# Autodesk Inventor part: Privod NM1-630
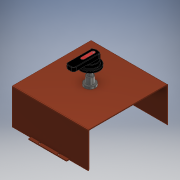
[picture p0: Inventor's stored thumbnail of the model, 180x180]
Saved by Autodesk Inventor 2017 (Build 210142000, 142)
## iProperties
Part Number: Privod NM1-630
Material: Типовые
Document SubType Name: Modeling
Designer: RSagdiev
Density: 1 g/cm^3
Appearance: По умолчанию
Author: RSagdiev
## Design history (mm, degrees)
sketch "Эскиз1"
  geometry: L1 (-45.5, 101.75)-(45.5, 101.75); L2 (45.5, 101.75)-(45.5, 93.25); L3 (45.5, 93.25)-(24.75, 93.25); L4 (-45.5, 93.25)-(-45.5, 101.75); L5 (0, 0)-(119.698, 0); L6 (0, 0)-(-104.809, 0); L7 (0, 94.88)-(0, -60.954); L8 (-24.75, 93.25)-(-20.75, 93.25); L9 (-20.75, 93.25)-(-20.75, 98.25); L10 (-22.75, 100.25)-(-22.75, 100.25); L11 (-24.75, 98.25)-(-24.75, 93.25); L12 (20.75, 93.25)-(20.75, 98.25); L13 (22.75, 100.25)-(22.75, 100.25); L14 (24.75, 93.25)-(20.75, 93.25); L15 (24.75, 98.25)-(24.75, 93.25); L16 (-24.75, 93.25)-(-45.5, 93.25); L17 (-20.75, 93.25)-(-24.75, 93.25); L18 (20.75, 93.25)-(-20.75, 93.25); L19 (24.75, 93.25)-(20.75, 93.25); A1 r 2 centre (-22.75, 98.25) between (-22.75, 100.25) and (-24.75, 98.25); A2 r 2 centre (-22.75, 98.25) between (-20.75, 98.25) and (-22.75, 100.25); A3 r 2 centre (22.75, 98.25) between (22.75, 100.25) and (20.75, 98.25); A4 r 2 centre (22.75, 98.25) between (24.75, 98.25) and (22.75, 100.25); 5 further points
  constraints: 38 end point, 10 point on line, 10 symmetric about line, 8 parallel, 8 point on circle, 4 centre point, 4 horizontal, 4 tangent, 2 perpendicular, 1 concentric, 1 midpoint, 1 vertical, 2 other
  dimensions: "d0" = 93.25 distance between parallel lines of L3 L6 (= 0.5 x Высота); "d1" = 8.5 distance of L1.end L2.end; "d2" = 91 distance between parallel lines of L2 L4 (= 0.5 x Ширина); "d3" = 4 distance of point (-24.75, 100.25) point (-20.75, 100.25); "d4" = 7 distance of point (-20.75, 100.25) L8.end; "d5" = 2 radius of A1 (derived); "d6" = 22.75 distance from line of L4 A1.centre (= 0.25 x d2)
extrude "Выдавливание1" new body sketch "Эскиз1" distance "d7" = 2; taper "d8" = 0 deg
mirror "Зеркальное отражение1"
sketch "Эскиз2"
  geometry: L1 (-45.5, 101.75)-(-45.5, 93.25) reference; L2 (45.5, 93.25)-(45.5, 101.75) reference; L3 (-45.5, -101.75)-(-45.5, -93.25) reference; L4 (45.5, -93.25)-(45.5, -101.75) reference; L5 (-91, 95.25)-(91, 95.25); L6 (91, 95.25)-(91, 93.25); L7 (91, 93.25)-(-91, 93.25); L8 (-91, 93.25)-(-91, 95.25); L9 (-45.5, 93.25)-(-24.75, 93.25) reference
  constraints: 8 end point, 2 parallel, 1 collinear, 1 horizontal, 1 perpendicular
  dimensions: "d13" = 182 distance of L5.start L5.end (= Ширина); "d14" = 2 distance of L5.end L6.end; "d15" = 45.5 distance between parallel lines of L1 L8 (= 0.25 x d13)
extrude "Выдавливание2" join sketch "Эскиз2" distance "d11" = 85 (computed from H1); taper "d12" = 0 deg
mirror "Зеркальное отражение2"
sketch "Эскиз3"
  geometry: L1 (-91, 95.25)-(-45.5, 95.25) reference; L2 (91, -95.25)-(-91, -95.25) reference; L3 (-91, 95.25)-(91, 95.25); L4 (91, 95.25)-(91, -95.25); L5 (91, -95.25)-(-91, -95.25); L6 (-91, -95.25)-(-91, 95.25); 1 further point
  constraints: 8 end point, 2 parallel, 1 horizontal, 1 perpendicular
extrude "Выдавливание3" join sketch "Эскиз3" distance "d16" = 2; taper "d17" = 0 deg
fillet "Сопряжение1" dims "d18" = 2
sketch "Эскиз4"
  geometry: L1 (91, -91.25)-(-91, -91.25) reference; L2 (91, -91.25)-(91, 91.25) reference; L3 (-91, 91.25)-(91, 91.25) reference; L4 (-91, 91.25)-(-91, -91.25) reference; L5 (-91, 91.25)-(-91, -91.25) reference; L6 (-91, -91.25)-(91, 91.25); L7 (91, -91.25)-(91, 91.25) reference; L8 (-91, 91.25)-(91, -91.25); C1 r 5 at (0, 0); 1 further point
  constraints: 4 end point, 1 centre point, 1 coincident
  dimensions: "d19" = 10 diameter of C1
extrude "Выдавливание4" cut sketch "Эскиз4" distance "d20" = 10; taper "d21" = 0 deg
sketch "Эскиз5"
  geometry: C1 r 5 at (0, 0) reference; C2 r 5 at (0, 0); C3 r 8 at (0, 0); 1 further point
  constraints: 2 centre point, 2 coincident
  dimensions: "d22" = 16 diameter of C3
extrude "Выдавливание5" new body sketch "Эскиз5" distance "d23" = 29.66667 (= 0.333333 x H1); taper "d24" = 0 deg
sketch "Эскиз6"
  geometry: C1 r 5 at (0, 0) reference; C2 r 5 at (0, 0); 1 further point
  constraints: 1 centre point, 1 coincident
extrude "Выдавливание6" new body sketch "Эскиз6" distance "d25" = 79.66667 (computed from H1); taper "d26" = 0 deg
sketch "Эскиз7"
  geometry: C1 r 5 at (0, 0) reference; C2 r 13 at (0, 0); C3 r 8 at (0, 0); C4 r 5 at (0, 0); 1 further point
  constraints: 3 centre point, 3 coincident
  dimensions: "d27" = 26 diameter of C2; "d28" = 16 diameter of C3; "d29" = 10 diameter of C4
extrude "Выдавливание7" new body sketch "Эскиз7" distance "d30" = 5; taper "d31" = 0 deg
extrude "Выдавливание8" join sketch "Эскиз7" distance "d32" = 20; taper "d33" = 0 deg
sketch "Эскиз8"
  geometry: C1 r 7 at (0, 0); 1 further point
  constraints: 1 centre point, 1 coincident
  dimensions: "d34" = 14 diameter of C1
extrude "Выдавливание9" new body sketch "Эскиз8" distance "d35" = 3; taper "d36" = 0 deg
fillet "Сопряжение2" dims "d37" = 3
sketch "Эскиз9"
  geometry: L1 (1, 13.17)-(-1, 13.17); L2 (-1, 13.17)-(-1, -13.17); L3 (-1, -13.17)-(1, -13.17); L4 (1, -13.17)-(1, 13.17); L5 (1, 13.17)-(-1, -13.17); L6 (-1, 13.17)-(1, -13.17); L7 (17.109, -1)-(-17.109, -1); L8 (-17.109, -1)-(-17.109, 1); L9 (-17.109, 1)-(17.109, 1); L10 (17.109, 1)-(17.109, -1); L11 (17.109, -1)-(-17.109, 1); L12 (-17.109, -1)-(17.109, 1); C1 r 4 at (0, 0) reference; C2 r 5 at (0, 0) reference; 1 further point
  constraints: 24 end point, 4 midpoint, 4 parallel, 2 horizontal, 2 perpendicular
  dimensions: "d38" = 2 distance of L3.end L2.end; "d39" = 2 distance of L7.end L8.end
extrude "Выдавливание10" cut sketch "Эскиз9" distance "d40" = 1; taper "d41" = 0 deg
sketch "Эскиз10"
  geometry: C1 r 17.5 at (0, 0); A1 r 4 centre (0, 0) between (1, -3.873) and (3.873, -1) reference; 1 further point
  constraints: 1 centre point, 1 coincident
  dimensions: "d42" = 35 diameter of C1
extrude "Выдавливание11" new body sketch "Эскиз10" distance "d43" = 6; taper "d44" = 0 deg; dims "d48" = 3, "d49" = 0
sketch "Эскиз11"
  geometry: C1 r 7 at (0, 0); C2 r 22.5 at (0, 0); 1 further point
  constraints: 2 centre point, 1 coincident
  dimensions: "d45" = 45 diameter of C2
extrude "Выдавливание12" join sketch "Эскиз11" distance "d46" = 6; taper "d47" = 0 deg
sketch "Эскиз12"
  geometry: L1 (-4, -49.361)-(4, -49.361); L2 (10, -43.361)-(10, 10.738); L3 (-10, 10.738)-(-10, -43.361); L4 (-10, -49.361)-(10, 14.361); L5 (10, -49.361)-(-10, 14.361); L6 (-12, 12.738)-(12, 12.738); A1 r 17.5 centre (0, 0) between (10, 14.361) and (0, -17.5) reference; A2 r 17.5 centre (0, 0) between (10, 14.361) and (0, -17.5) reference; A3 r 6 centre (-4, -43.361) between (-10, -43.361) and (-4, -49.361); A4 r 6 centre (4, -43.361) between (4, -49.361) and (10, -43.361); A5 r 2 centre (-12, 10.738) between (-10, 10.738) and (-12, 12.738); A6 r 2 centre (12, 10.738) between (12, 12.738) and (10, 10.738); A7 r 17.5 centre (0, 0) between (12, 12.738) and (-12, 12.738)
  constraints: 16 point on circle, 12 end point, 8 tangent, 6 point on line, 5 centre point, 2 equal radius, 2 horizontal, 2 midpoint, 1 coincident, 1 parallel, 1 perpendicular
  dimensions: "d63" = 20 distance of L4.end L5.end; "d64" = 6 radius of A3; "d66" = 10 distance from line of A1.centre L3; "d67" = 2 radius of A5; "d68" = 2 radius of A6 (derived)
extrude "Выдавливание13" join sketch "Эскиз12" distance "d55" = 10; taper "d56" = 0 deg
fillet "Сопряжение9" dims "d69" = 1
fillet "Сопряжение10" dims "d70" = 1
sketch "Эскиз13"
  geometry: L1 (0, 7.748)-(0, -17.5); L2 (-4, 7.748)-(-4, -17.5); L3 (4, -17.5)-(4, 7.748); A1 r 17.5 centre (0, 0) between (17.5, 0) and (0, -17.5) reference; A2 r 4 centre (0, 7.748) between (4, 7.748) and (-4, 7.748); A3 r 4 centre (0, -17.5) between (-4, -17.5) and (4, -17.5); 2 further points
  constraints: 8 end point, 5 point on circle, 4 tangent, 2 centre point, 1 midpoint, 1 parallel, 1 vertical
  dimensions: "d71" = 8 diameter of A3
extrude "Выдавливание14" cut sketch "Эскиз13" distance "d72" = 0.1; taper "d73" = 0 deg
sketch "Эскиз14"
  geometry: L1 (0, 9.652)-(1.649, 6.796); L2 (1.649, 6.796)-(-1.649, 6.796); L3 (-1.649, 6.796)-(0, 9.652); A1 r 4 centre (0, 7.748) between (4, 7.748) and (-4, 7.748) reference; 2 further points
  constraints: 6 end point, 1 coincident, 7 other
extrude "Выдавливание15" join sketch "Эскиз14" distance "d74" = 0.1; taper "d75" = 0 deg
node "Твердое тело1"
node "Спроецированная петля1"
node "Твердое тело2"
node "Твердое тело3"
node "Твердое тело4"
node "Твердое тело5"
node "Спроецированная петля2"
node "Твердое тело6"
node "Спроецированная петля3"
other parameters: "H1" = 89 [user parameter; used in 3 equation terms], "Высота" = 186.5 [user parameter; used in 1 equation term], "Ширина" = 182 [user parameter; used in 2 equation terms]
